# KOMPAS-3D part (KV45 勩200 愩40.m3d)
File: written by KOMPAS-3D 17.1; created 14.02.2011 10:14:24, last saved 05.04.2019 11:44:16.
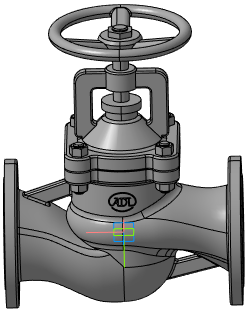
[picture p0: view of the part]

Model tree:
1. Плоскость XY
2. Плоскость ZX
3. Плоскость ZY
4. Ось X
5. Ось Y
6. Ось Z
7. Начало координат
8. Операция без истории:4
